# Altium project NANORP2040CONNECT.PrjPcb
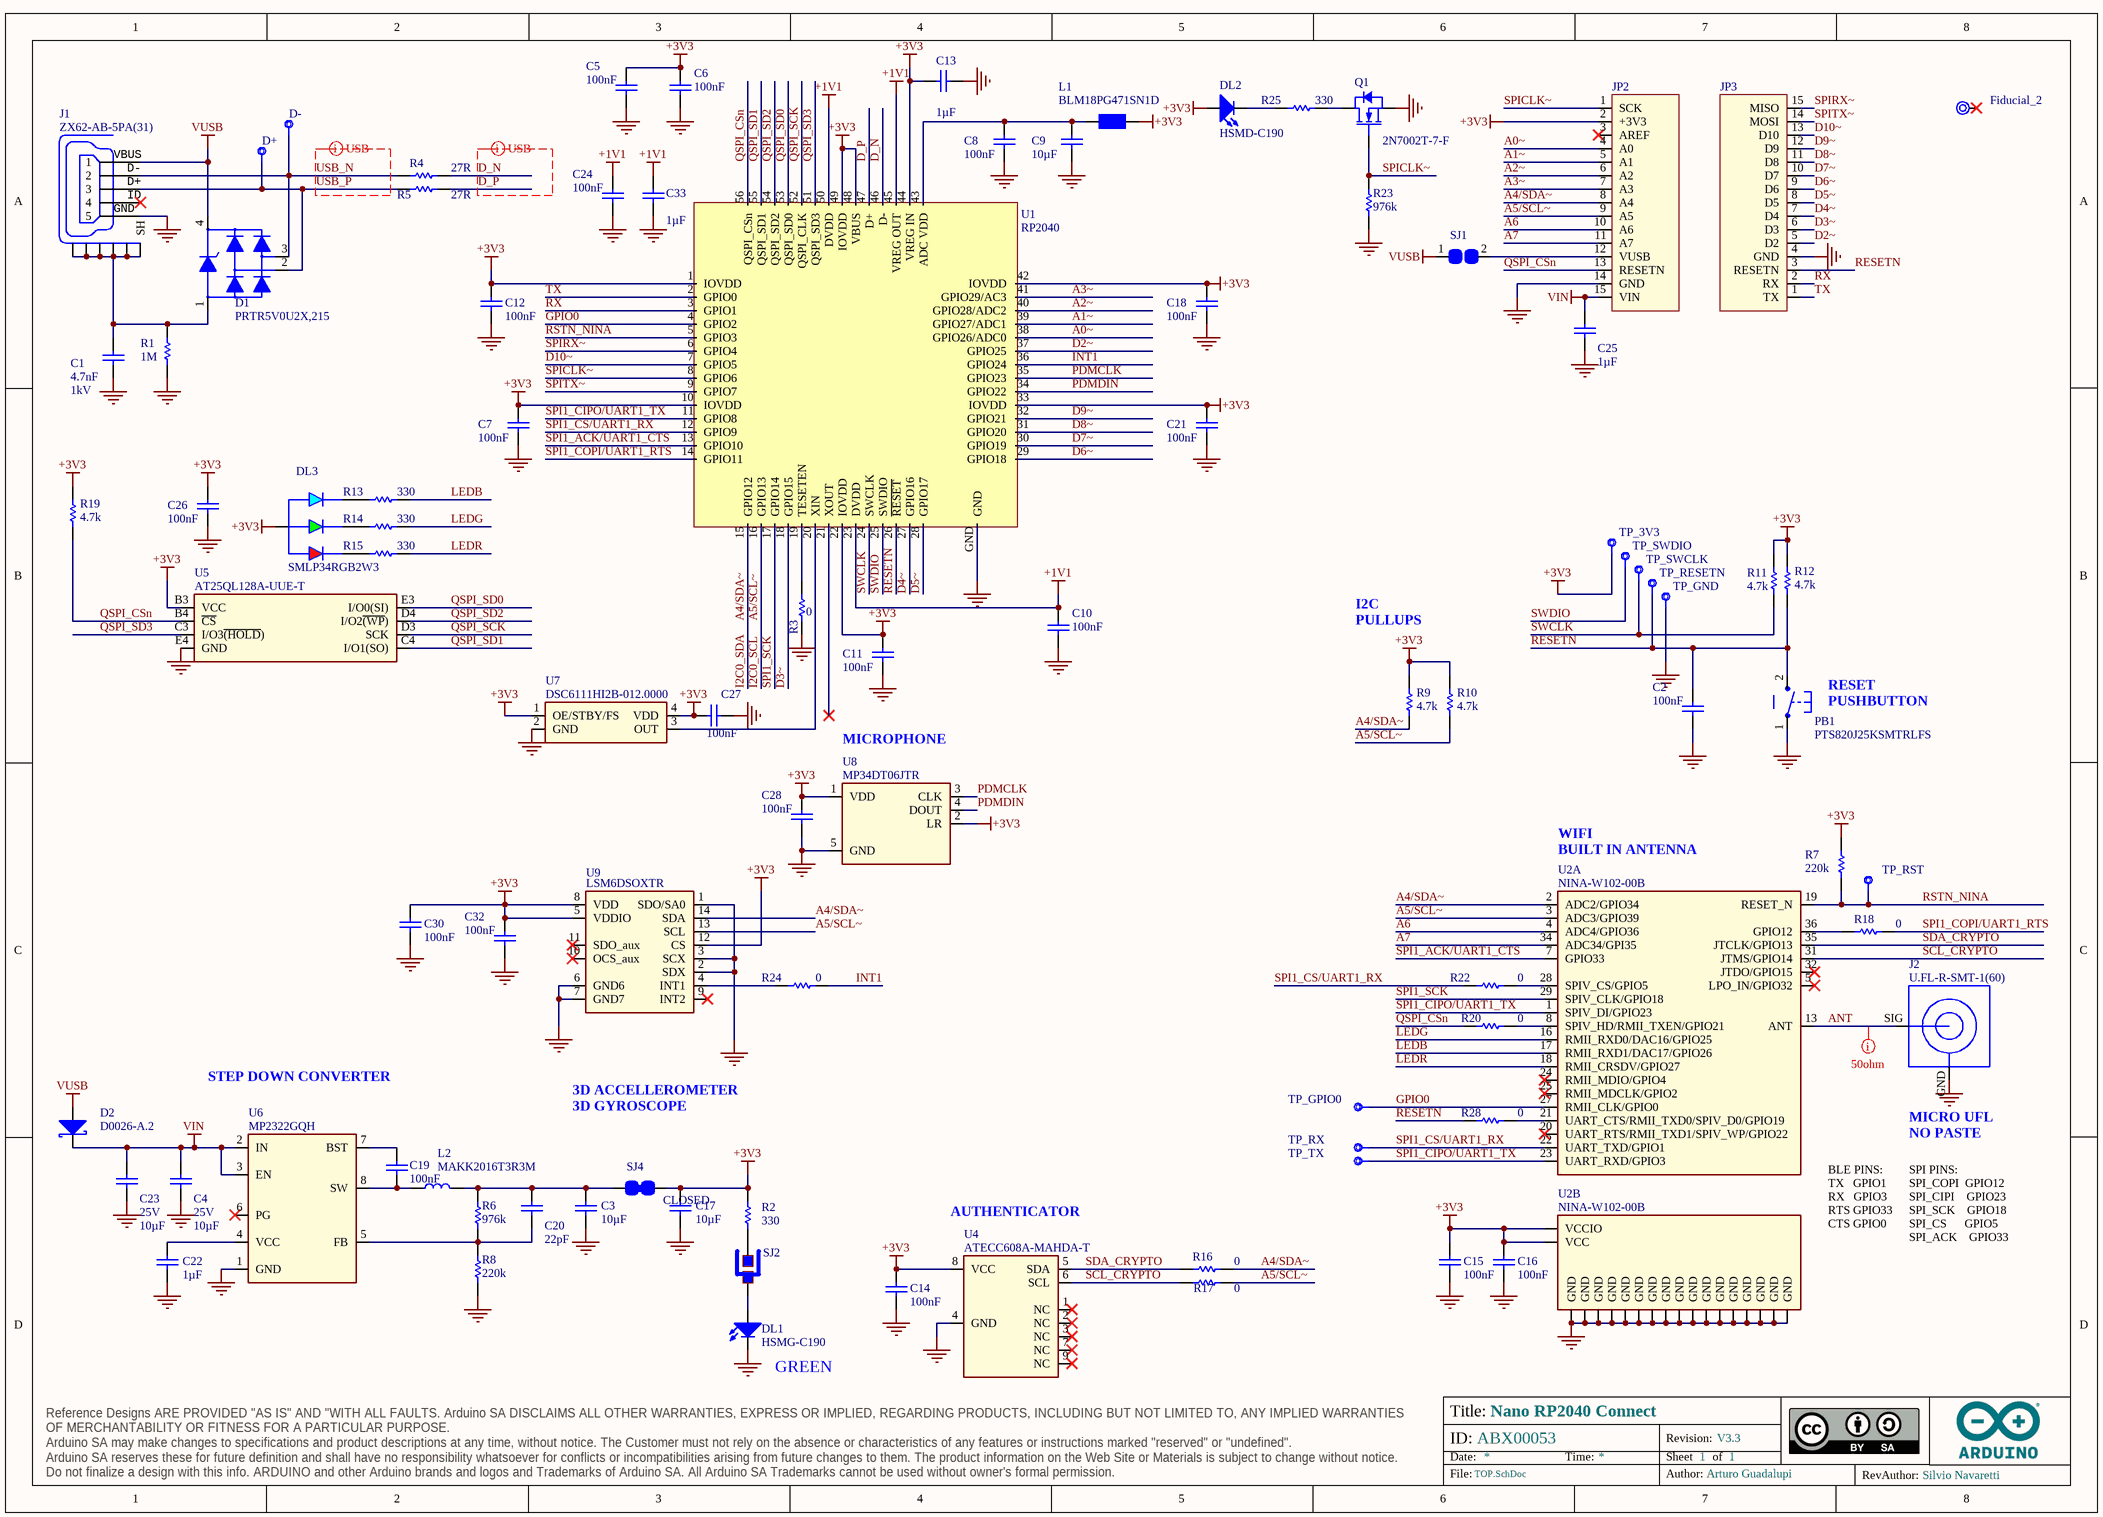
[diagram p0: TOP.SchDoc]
THICKNESS: 1.6mm; THD: _; TBD: _; TABS: X; SOLDERMASK_TOP: X; SOLDERMASK_PEELABLE_TOP: _; SOLDERMASK_PEELABLE_COLOR: _; SOLDERMASK_PEELABLE_BOTTOM: _; SOLDERMASK_COLOR: BLUE; SOLDERMASK_BOTTOM: X; SN/PB: _; SMD: X; SKU: ABX00053; SILK_TOP: X; SILK_COLOR: WHITE; SILK_BOTTOM: X; SCORING: X; RIGID/FLEX: _; RIGID: X; Revision: V3.3; PRESSFIT: _; POLYMIDE: _; PCB_SIZE: 43.18 mm x 17.78 mm; PANEL_SIZE: 211.00 mm x 180.46mm; PANEL_REQUESTED: _; PANEL_PROVIDED: X; PANEL_NO: _; N_FIGURES: 28; NLAYERS: 4; NI/AU: _; MIN_TRACK_WIDTH_OUTER: 0.15mm; MIN_TRACK_WIDTH_INNER: 0.15mm; MIN_INSULATION_OUTER: 0.15mm; MIN_INSULATION_INNER: 0.15mm; MILLING: X; IPCNA: X; IPC3: _; IPC2: _; IPC1: _; HOLE_TOP_BOTTOM: X; HAL_LF: _; HAL: _; FR4_HTG: _; FR4: X; FLEX: _; FINISH_TBD: _; ENIG: X; EDGE_PLATING: _; DRILLS_SOLDER_FILLING: X; DRILLS_SLOT: _; DRILLS_RESIN_FILLING: _; DRILLS_PRESSFIT: _; DRILLS_LASER: _; DRILLS_FULL: X; DRILLS_COPPER_FILLING: _; DRILLS_BURIED: _; DRILLS_BLIND: _; BGA: X; Author: Arturo Guadalupi; ADJUSTMENTS: _
1 sheet, 92 parts. Net scope: global (net labels, ports and power ports of the same name join across sheets).
Board files: NANORP2040Connect.PcbDoc, NANORP2040Connect_Panel.PcbDoc

## Sheet TOP.SchDoc: Nano RP2040 Connect
size A3; Author: Arturo Guadalupi; DocumentNumber: ABX00053; Revision: V3.3; SheetNumber: 1; SheetTotal: 1; RevAuthor: Silvio Navaretti

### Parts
C1  value 4.7nF  Voltage: 1kV  [CAP-0805]  (hidden comment: C0805C472KDRACTU)
C2  value 100nF  [CAP-0201]  (hidden comment: CL03A104KP3NNNC)
C3  value 10µF  [CAP-0402]  (hidden comment: GRM155R60J106ME05D)
C4  value 10µF  Voltage: 25V  [CAP-0603]  (hidden comment: GRM188R61E106MA73J)
C5  value 100nF  [CAP-0201]  (hidden comment: CL03A104KP3NNNC)
C6  value 100nF  [CAP-0201]  (hidden comment: CL03A104KP3NNNC)
C7  value 100nF  [CAP-0201]  (hidden comment: CL03A104KP3NNNC)
C8  value 100nF  [CAP-0201]  (hidden comment: CL03A104KP3NNNC)
C9  value 10µF  [CAP-0603]  (hidden comment: CC0603MRX5R5BB106)
C10  value 100nF  [CAP-0201]  (hidden comment: CL03A104KP3NNNC)
C11  value 100nF  [CAP-0201]  (hidden comment: CL03A104KP3NNNC)
C12  value 100nF  [CAP-0201]  (hidden comment: CL03A104KP3NNNC)
C13  value 1µF  [CAP-0201]  (hidden comment: GRM033R60J105MEA2D)
C14  value 100nF  [CAP-0201]  (hidden comment: CL03A104KP3NNNC)
C15  value 100nF  [CAP-0201]  (hidden comment: CL03A104KP3NNNC)
C16  value 100nF  [CAP-0201]  (hidden comment: CL03A104KP3NNNC)
C17  value 10µF  [CAP-0402]  (hidden comment: GRM155R60J106ME05D)
C18  value 100nF  [CAP-0201]  (hidden comment: CL03A104KP3NNNC)
C19  value 100nF  [CAP-0201]  (hidden comment: CL03A104KP3NNNC)
C20  value 22pF  [CAP-0402]  (hidden comment: C0402C220J5GAC7411)
C21  value 100nF  [CAP-0201]  (hidden comment: CL03A104KP3NNNC)
C22  value 1µF  [CAP-0201]  (hidden comment: GRM033R60J105MEA2D)
C23  value 10µF  Voltage: 25V  [CAP-0603]  (hidden comment: GRM188R61E106MA73J)
C24  value 100nF  [CAP-0201]  (hidden comment: CL03A104KP3NNNC)
C25  value 1µF  [CAP-0402]  (hidden comment: C0402C105K8PACTU)
C26  value 100nF  [CAP-0201]  (hidden comment: CL03A104KP3NNNC)
C27  value 100nF  [CAP-0201]  (hidden comment: CL03A104KP3NNNC)
C28  value 100nF  [CAP-0201]  (hidden comment: CL03A104KP3NNNC)
C30  value 100nF  [CAP-0201]  (hidden comment: CL03A104KP3NNNC)
C32  value 100nF  [CAP-0201]  (hidden comment: CL03A104KP3NNNC)
C33  value 1µF  [CAP-0201]  (hidden comment: GRM033R60J105MEA2D)
D1  PRTR5V0U2X,215  [SOT190P230X110-4N]
D2  D0026-A.2  [SOD123-1]
D+  CMP-018-0005-A.3  [TP-1.00MM]  (value not drawn)  (no BOM)
D-  CMP-018-0005-A.3  [TP-1.00MM]  (value not drawn)  (no BOM)
DL1  HSMG-C190  [LEDC1608X80N-AK]
DL2  HSMD-C190  [LEDC1608X80N-AK]
DL3  SMLP34RGB2W3  [SMLP34RGB2W]
Fiducial_2  Fiducial mark 1mm with 2mm solder  [Fiducial mark 1mm with circle-Footprint-1]  (value not drawn)  (no BOM)
J1  ZX62-AB-5PA(31)  [ZX62-AB-5PA]
J2  U.FL-R-SMT-1(60)  [U.FL-R-SMT-1(60)-1]
JP2  PINHD-1X15-NANO  [New footprint 1]  (value not drawn)
JP3  PINHD-1X15-NANO-DIGITAL-CASTELLATED  [PINHD-1X14_5VF]  (value not drawn)
L1  BLM18PG471SN1D  [L-0603]
L2  MAKK2016T3R3M  [MAKK2016T3R3M-Footprint-1]
PB1  PTS820J25KSMTRLFS  [C&K_PTS820_NO_HOLES-1]
Q1  2N7002T-7-F  [SOT523]
R1  value 1M  [RES-0402]  (hidden comment: CRCW04021M00FKED)
R2  value 330  [RES-0201]  (hidden comment: AC0201FR-07330RL)
R3  value 0  [RES-0201]  (hidden comment: CRCW02010000Z0ED)
R4  value 27R  [RES-0201]  (hidden comment: CRCW020127R0FNED)
R5  value 27R  [RES-0201]  (hidden comment: CRCW020127R0FNED)
R6  value 976k  [RES-0201]  (hidden comment: RMCF0201FT976K)
R7  value 220k  [RES-0201]  (hidden comment: AC0201FR-07220KL)
R8  value 220k  [RES-0201]  (hidden comment: AC0201FR-07220KL)
R9  value 4.7k  [RES-0201]  (hidden comment: RC0201FR-074K7L)
R10  value 4.7k  [RES-0201]  (hidden comment: RC0201FR-074K7L)
R11  value 4.7k  [RES-0201]  (hidden comment: RC0201FR-074K7L)
R12  value 4.7k  [RES-0201]  (hidden comment: RC0201FR-074K7L)
R13  value 330  [RES-0201]  (hidden comment: AC0201FR-07330RL)
R14  value 330  [RES-0201]  (hidden comment: AC0201FR-07330RL)
R15  value 330  [RES-0201]  (hidden comment: AC0201FR-07330RL)
R16  value 0  [RES-0201]  (hidden comment: CRCW02010000Z0ED)
R17  value 0  [RES-0201]  (hidden comment: CRCW02010000Z0ED)
R18  value 0  [RES-0201]  (hidden comment: CRCW02010000Z0ED)
R19  value 4.7k  [RES-0201]  (hidden comment: RC0201FR-074K7L)
R20  value 0  [RES-0201]  (hidden comment: CRCW02010000Z0ED)
R22  value 0  [RES-0201]  (hidden comment: CRCW02010000Z0ED)
R23  value 976k  [RES-0201]  (hidden comment: RMCF0201FT976K)
R24  value 0  [RES-0201]  (hidden comment: CRCW02010000Z0ED)
R25  value 330  [RES-0201]  (hidden comment: AC0201FR-07330RL)
R28  value 0  [RES-0201]  (hidden comment: CRCW02010000Z0ED)
SJ1  SMD solder JUMPER 0805  [SJ]  (value not drawn)  (no BOM)
SJ2  Solder Jumper 0201 CLOSED with HUG  [Solder Jumper Maze-Footprint-1]  (value not drawn)
SJ4  SMD solder JUMPER CLOSED  [SJ]  (value not drawn)  (no BOM)
TP_3V3  CMP-018-0005-A.3  [TP-1.00MM]  (value not drawn)  (no BOM)
TP_GND  CMP-018-0005-A.3  [TP-1.00MM]  (value not drawn)  (no BOM)
TP_GPIO0  CMP-018-0005-A.3  [TP-1.00MM]  (value not drawn)  (no BOM)
TP_RESETN  CMP-018-0005-A.3  [TP-1.00MM]  (value not drawn)  (no BOM)
TP_RST  CMP-018-0005-A.3  [TP-1.00MM]  (value not drawn)  (no BOM)
TP_RX  CMP-018-0005-A.3  [TP-1.00MM]  (value not drawn)  (no BOM)
TP_SWCLK  CMP-018-0005-A.3  [TP-1.00MM]  (value not drawn)  (no BOM)
TP_SWDIO  CMP-018-0005-A.3  [TP-1.00MM]  (value not drawn)  (no BOM)
TP_TX  CMP-018-0005-A.3  [TP-1.00MM]  (value not drawn)  (no BOM)
U1  RP2040  [QFN40P700X700X90_HS-57N]
U2  NINA-W102-00B  [NINA-W102]  (parts A,B of 2)
U4  ATECC608A-MAHDA-T  [UDFN8]
U5  AT25QL128A-UUE-T  [BGA21C50P6X6_301X328X52]
U6  MP2322GQH  [QFN50P150X200X90-8L]
U7  DSC6111HI2B-012.0000  [DFN120P120X89-4M]
U8  MP34DT06JTR  [HCLGA]
U9  LSM6DSOXTR  [VFLGA14]

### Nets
+1V1: C10.1 C24.1 C33.2 U1.23(DVDD) U1.45(VREG_OUT) U1.50(DVDD)
+3V3: C5.1 C6.1 C7.1 C11.1 C12.1 C13.1 C14.1 C15.1 C16.1 C17.2 C18.1 C21.1 C26.1 C27.1 C28.1 C30.1 C32.1 DL2.A DL3.1(A) JP2.2(+3V3) L1.2 R2.2 R7.2 R9.2 R10.2 R11.2 R12.2 R19.2 SJ4.1 TP_3V3.X U1.1(IOVDD) U1.10(IOVDD) U1.22(IOVDD) U1.33(IOVDD) U1.42(IOVDD) U1.44(VREG_IN) U1.48(VBUS) U1.49(IOVDD) U2.9(VCCIO) U2.10(VCC) U4.8(VCC) U5.B3(VCC) U7.1(OE/STBY/FS) U7.4(VDD) U8.1(VDD) U8.2(LR) U9.5(VDDIO) U9.8(VDD) U9.12(CS)
GND: C1.1 C2.2 C3.1 C4.1 C5.2 C6.2 C7.2 C8.2 C9.1 C10.2 C11.2 C12.2 C13.2 C14.2 C15.2 C16.2 C17.1 C18.2 C21.2 C22.1 C23.1 C24.2 C25.1 C26.2 C27.2 C28.2 C30.2 C32.2 C33.1 DL1.C J1.5 J2.GND JP2.14(GND) JP3.4(GND) PB1.1 Q1.S R1.1 R3.1 R8.1 R23.1 TP_GND.X U1.GND U2.6(GND) U2.12(GND) U2.14(GND) U2.26(GND) U2.30(GND) U2.GND1(GND) U2.GND2(GND) U2.GND3(GND) U2.GND4(GND) U2.GND5(GND) U2.GND6(GND) U2.GND7(GND) U2.GND8(GND) U2.GND9(GND) U2.GND10(GND) U2.GND11(GND) U2.GND12(GND) U4.4(GND) U5.E4(GND) U6.1(GND) U7.2(GND) U8.5(GND) U9.1(SDO/SA0) U9.2(SDX) U9.3(SCX) U9.6(GND6) U9.7(GND7)
VIN: C4.2 C23.2 C25.2 D2.C JP2.15(VIN) U6.2(IN) U6.3(EN)
VUSB: D1.4 D2.A J1.1 SJ1.1
A0~: JP2.4(A0) U1.38(GPIO26/ADC0)
A1~: JP2.5(A1) U1.39(GPIO27/ADC1)
A2~: JP2.6(A2) U1.40(GPIO28/ADC2)
A3~: JP2.7(A3) U1.41(GPIO29/AC3)
A4/SDA~: JP2.8(A4) R9.1 R16.1 U1.15(GPIO12) U2.2(ADC2/GPIO34) U9.14(SDA)  [also labelled I2C0_SDA]
A5/SCL~: JP2.9(A5) R10.1 R17.1 U1.16(GPIO13) U2.3(ADC3/GPIO39) U9.13(SCL)  [also labelled I2C0_SCL]
A6: JP2.10(A6) U2.4(ADC4/GPIO36)
A7: JP2.11(A7) U2.34(ADC34/GPI35)
ANT: J2.SIG U2.13(ANT)
D2~: JP3.5(D2) U1.37(GPIO25)
D3~: JP3.6(D3) U1.18(GPIO15)
D4~: JP3.7(D4) U1.27(GPIO16)
D5~: JP3.8(D5) U1.28(GPIO17)
D6~: JP3.9(D6) U1.29(GPIO18)
D7~: JP3.10(D7) U1.30(GPIO19)
D8~: JP3.11(D8) U1.31(GPIO20)
D9~: JP3.12(D9) U1.32(GPIO21)
D10~: JP3.13(D10) U1.7(GPIO5)
D_N: R4.2 U1.46(D-)
D_P: R5.2 U1.47(D+)
GPIO0: TP_GPIO0.X U1.4(GPIO2) U2.27(RMII_CLK/GPIO0)
INT1: R24.2 U1.36(GPIO24)
LEDB: R13.2 U2.17(RMII_RXD1/DAC17/GPIO26)
LEDG: R14.2 U2.16(RMII_RXD0/DAC16/GPIO25)
LEDR: R15.2 U2.18(RMII_CRSDV/GPIO27)
PDMCLK: U1.35(GPIO23) U8.3(CLK)
PDMDIN: U1.34(GPIO22) U8.4(DOUT)
QSPI_CSn: JP2.13(RESETN) R19.1 R20.2 U1.56(QSPI_CSn) U5.B4(~{CS})
QSPI_SCK: U1.52(QSPI_CLK) U5.D3(SCK)
QSPI_SD0: U1.53(QSPI_SD0) U5.E3(I/O0(SI))
QSPI_SD1: U1.55(QSPI_SD1) U5.C4(I/O1(SO))
QSPI_SD2: U1.54(QSPI_SD2) U5.D4(I/O2~{(WP}))
QSPI_SD3: U1.51(QSPI_SD3) U5.C3(I/O3~{(HOLD}))
RESETN: C2.1 JP3.3(RESETN) PB1.2 R12.1 R28.2 TP_RESETN.X U1.26(~{RESET})
RSTN_NINA: R7.1 TP_RST.X U1.5(GPIO3) U2.19(RESET_N)
RX: JP3.2(RX) U1.3(GPIO1)
SCL_CRYPTO: R17.2 U2.31(JTMS/GPIO14) U4.6(SCL)
SDA_CRYPTO: R16.2 U2.35(JTCLK/GPIO13) U4.5(SDA)
SPI1_ACK/UART1_CTS: U1.13(GPIO10) U2.7(GPIO33)
SPI1_CIPO/UART1_TX: TP_TX.X U1.11(GPIO8) U2.1(SPIV_DI/GPIO23) U2.23(UART_RXD/GPIO3)
SPI1_COPI/UART1_RTS: R18.1 U1.14(GPIO11)
SPI1_CS/UART1_RX: R22.2 TP_RX.X U1.12(GPIO9) U2.22(UART_TXD/GPIO1)
SPI1_SCK: U1.17(GPIO14) U2.29(SPIV_CLK/GPIO18)
SPICLK~: JP2.1(SCK) Q1.G R23.2 U1.8(GPIO6)
SPIRX~: JP3.15(MISO) U1.6(GPIO4)
SPITX~: JP3.14(MOSI) U1.9(GPIO7)
SWCLK: R11.1 TP_SWCLK.X U1.24(SWCLK)
SWDIO: TP_SWDIO.X U1.25(SWDIO)
TX: JP3.1(TX) U1.2(GPIO0)
USB_N: D1.3 D-.X J1.2 R4.1
USB_P: D1.2 D+.X J1.3 R5.1
NetC1_2: C1.2 D1.1 J1.M1(SH) J1.M2(SH) J1.M3(SH) J1.M4(SH) J1.M5(SH) J1.M6(SH) R1.2
NetC3_2: C3.2 C20.2 L2.2 R6.2 SJ4.2
NetC8_1: C8.1 C9.2 L1.1 U1.43(ADC_VDD)
NetC19_1: C19.1 L2.1 U6.8(SW)
NetC19_2: C19.2 U6.7(BST)
NetC20_1: C20.1 R6.1 R8.2 U6.5(FB)
NetC22_2: C22.2 U6.4(VCC)
NetDL1_A: DL1.A SJ2.1
NetDL2_C: DL2.C R25.1
NetDL3_2: DL3.2(RED_C) R15.1
NetDL3_3: DL3.3(BLUE_C) R13.1
NetDL3_4: DL3.4(GREEN_C) R14.1
NetJP2_12: JP2.12(VUSB) SJ1.2
NetQ1_D: Q1.D R25.2
NetR2_1: R2.1 SJ2.2
NetR3_2: R3.2 U1.19(TESETEN)
NetR18_2: R18.2 U2.36(GPIO12)
NetR20_1: R20.1 U2.8(SPIV_HD/RMII_TXEN/GPIO21)
NetR22_1: R22.1 U2.28(SPIV_CS/GPIO5)
NetR24_1: R24.1 U9.4(INT1)
NetR28_1: R28.1 U2.21(UART_CTS/RMII_TXD0/SPIV_D0/GPIO19)
NetU1_20: U1.20(XIN) U7.3(OUT)

Not connected (* = marked no-connect by the designer): Fiducial_2 1*; J1 4*; JP2 3(AREF)*; U1 21(XOUT)*; U2 5(LPO_IN/GPIO32)* 20(UART_RTS/RMII_TXD1/SPIV_WP/GPIO22)* 24(RMII_MDIO/GPIO4)* 25(RMII_MDCLK/GPIO2)* 32(JTDO/GPIO15)*; U4 1(NC)* 2(NC)* 3(NC)* 7(NC)* 9(NC)*; U6 6(PG)*; U9 9(INT2)* 10(OCS_aux)* 11(SDO_aux)*

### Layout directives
differential pair; differential pair class USB: D_N, D_P, USB_N, USB_P
net class 50ohm: ANT

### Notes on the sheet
- I2C
  PULLUPS
- (near PB1) RESET
  PUSHBUTTON
- (near U8) MICROPHONE
- WIFI
  BUILT IN ANTENNA
- STEP DOWN CONVERTER
- 3D ACCELLEROMETER
  3D GYROSCOPE
- (near J2) MICRO UFL
  NO PASTE
- (near U4) AUTHENTICATOR
- (near U2) BLE PINS:
  TX   GPIO1
  RX   GPIO3
  RTS GPIO33
  CTS GPIO0
- SPI PINS:
  SPI_COPI  GPIO12
  SPI_CIPI    GPIO23
  SPI_SCK    GPIO18
  SPI_CS      GPIO5
  SPI_ACK    GPIO33
- (near DL1) GREEN

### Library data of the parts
C1 = C0059-A.9: CAP CHIP 0805 4.7nF 1000V X7R 10%; Manufacturer: KEMET; Code Arduino: 0689
C2 C5-C8 C10-C12 C14-C16 C18 C19 C21 C24 C26-C28 C30 C32 = C0113-A.1: CAP CHIP 0201 100nF 10V X5R 10%; Manufacturer: Samsung Electro-Mechanics; Code Arduino: C0113
C3 C17 = C0091-A.8: CAP CHIP 0402 10UF X5R 6.3V 20%; Manufacturer: Murata; Code Arduino: C0091
C4 C23 = C0047-A.12: CAP CHIP 0603 10uF 25V X5R 20%; Part Number: C1608X5R1A226MT000N; Manufacturer: Murata; Code Arduino: 2213
C9 = C0046-A.9: CAP CHIP 0603 10uF 6V3 X5R 20% Bob; Manufacturer: Yageo; Code Arduino: A5193; Voltage: 6.3V
C13 C22 C33 = C0002-A.9: CAP CHIP 0201 1UF 6.3V X5R 20%; Manufacturer: Murata; Code Arduino: A5520
C20 = C0029-A.9: CAP CHIP 0402 22pF 50V C0G 5%; Manufacturer: KEMET; Code Arduino: 0137
C25 = C0017-A.9: CAP CHIP 0402 1uF 10V X5R 10%; Manufacturer: KEMET; Code Arduino: 0133
D1 = D0025-A.3: TVS ARRAY 4LIN.8kV 1pF SOT143B; Manufacturer: Nexperia; Device Type: ESD protection; Code Arduino: 2209
D2 = D0026-A.2: DIODE SCHOTTKY SMD 1A 40V SOD123FL; Manufacturer: Nexperia; Part Number: PMEG6020AELRX; Code Arduino: 2208
D+ D- TP_3V3 TP_GND TP_GPIO0 TP_RESETN TP_RST TP_RX TP_SWCLK TP_SWDIO TP_TX = UT0013-A.2: Test point 1.00mm
DL1 = L0009-A.4: LED SMD 0603 GREEN/568 15mcd 120^; Manufacturer: Broadcom; Code Arduino: 2204
DL2 = L0007-A.4: LED SMD 0603 ORANGE604 8mcd DIFF.; Manufacturer: Broadcom; Code Arduino: 2245
DL3 = L0014-A.5: LED RGB DIFFUSED PICOLED SMD; Manufacturer: ROHM Semiconductor; Forward Current: 20mA; Lens Style: Rectangular; Dominant Wavelength: 470nm; Forward Voltage: 3V; Test Current: 5mA; Luminous Intensity: 45mcd; Code Arduino: A5469; Lens Color: White
Fiducial_2 = UT0024-A.6
J1 = J0039-A.5: CONN USB MICRO F/90^ SMD TipoAB 5x1; Manufacturer: Hirose; Code Arduino: 2219
J2 = J0042-A.4: CONN Micro UFL NO PASTE; Manufacturer: Hirose; Code Arduino: A5364
JP2 = J0055-A.4: CONN THD SOCKET F/1/D 15V JANALOG NANO-TYPE; Code Arduino: A5563
JP3 = J0183-A.1: CONN THD SOCKET F/1/D 15V JDIGITAL NANO-TYPE CASTELLATED; Code Arduino: A5564
L1 = I0006-A.3: FERRITE SMD 0603 470R 1A 0.2R; Manufacturer: Murata; DC Resistance (DCR): 200mR; Tolerance: 25%; Impedance: 470µH; Code Arduino: 2200; Test Frequency: 100MHz
L2 = I0045-A.5: IND CHIP 0806 3.3 uH 20% 1.2A; Manufacturer: Taiyo Yuden; Max DC Current: 1.15A; Core Material: Metal; DC Resistance (DCR): 255mR; Code Arduino: I0045; Test Frequency: 2MHz; Inductance: 3.3uH; Shielding: Shielded
PB1 = B0012-A.3: PUSHBUTTON SMD PTS820 NO ANCHORS; Manufacturer: C&K; Actuator Type: Standard; Code Arduino: A5506; Mechanical Life: 100000Cycles
Q1 = T0003-A.2: MOSFET N-CH 60V 115mA SOT523; Manufacturer: Diodes Inc.; Device Type: Mosfet N-CH SMD; Code Arduino: 2368
R1 = R0058-A.5: RES CHIP 0402 1M 1% 1/16W; Manufacturer: Vishay; Power: 63mW; Code Arduino: 0139
R2 = R0149-A.4: RES CHIP 0201 330R 1% 1/20W; Manufacturer: Yageo; Power: 50mW; Code Arduino: R0149
R3 R16-R18 R20 R22 R28 = R0140-A.4: RES CHIP 0201 0R 1/20W 5%; Manufacturer: Vishay; Power: 50mW; Code Arduino: R0140
R4 R5 = R0197-A.2: RES CHIP 0201 27R 1/20W 5%; Manufacturer: Vishay; Tolerance: 1%; Power: 50mW; Code Arduino: R0197
R6 R23 = R0198-A.1: RES CHIP 0201 976k 1/20W 1%; Manufacturer: Stackpole Electronics Inc; Code Arduino: R0198
R7 R8 = R0199-A.1: RES CHIP 0201 220k 1% 1/20W; Manufacturer: Yageo; Code Arduino: R0199
R9-R12 R19 = R0151-A.4: RES CHIP 0201 4K7 1% 1/20W; Manufacturer: Yageo; Power: 50mW; Code Arduino: A5521
R13-R15 R25 = R0149-A.4: RES CHIP 0201 330R 1% 1/20W; Manufacturer: Yageo; Code Arduino: R0149; Power: 50mW
R24 = R0140-A.4: RES CHIP 0201 0R 1/20W 5%; Manufacturer: Vishay; Code Arduino: R0140; Power: 50mW
SJ1 = UT0002-A.3: Solder Jumper 0805
SJ2 = UT0033-A.6: Part Number: CRCW02010000Z0ED; Manufacturer: Vishay; Code Arduino: R0140
SJ4 = UT0006-A.10: Solder Jumper shorted pads
U1 = U0177-A.6: IC MICROCONTROLLER RASPBERRY PI; Code Arduino: U0177; Device Type: MCU
U2 = M0002-A.5: MODULE ESP32 WiFi/BLE; Manufacturer: UBlox
U4 = U0034-A.4: IC AUTHENTICATION CHIP UDFN8; Manufacturer: Microchip
U5 = U0175-A.2: IC FLASH 128M SPI 21WLCSP; Manufacturer: Adesto Technologies; Code Arduino: U0175
U6 = U0072-A.5: IC STEP DOWN CONV 1A 22V QFN8; Manufacturer: Monolithic Power Systems; Code Arduino: U0072
U7 = X0013-A.3: MEMS OSC 12MHz VDD 1.7V to 3.6V VFLGA 1.6mm x 1.2mm; Manufacturer: Microchip; Code Arduino: X0013
U8 = U0074-A.4: SENS MEMS AUDIO OMNIDIRECTIONAL; Manufacturer: STMicroelectronics; Code Arduino: A5470; Device Type: SENSOR
U9 = U0179-A.4: IMU ACCEL/GYRO I2C/SPI 14VFLGA; Manufacturer: STMicroelectronics; Code Arduino: U0179; Max Supply Voltage: 3.6V; Min Supply Voltage: 1.7V

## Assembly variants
WITH_HEADERS: not fitted C25 C34 R7 U3
NO_HEADERS: not fitted C25 C34 JP2 JP3 R7 U3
